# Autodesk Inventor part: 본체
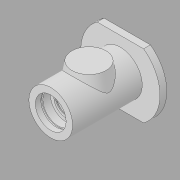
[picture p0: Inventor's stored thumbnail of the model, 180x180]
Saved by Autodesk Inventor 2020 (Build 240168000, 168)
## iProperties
Created: 2022-05
Part Number: 본체
Material: 일반
Document SubType Name: Modeling
Designer: User
Density: 1 g/cm^3
Appearance: 기본값
Author: User
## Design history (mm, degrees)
sketch "스케치1"
  geometry: L1 (-125, -47)-(125, -47); L2 (125, -47)-(125, 47); L3 (125, 47)-(-125, 47); L4 (-125, 47)-(-125, -47); L5 (-125, -47)-(125, 47); L6 (125, -47)-(-125, 47); C1 r 58 at (0, 0); 5 further points
  constraints: 12 end point, 2 midpoint, 2 parallel, 1 centre point, 1 coincident, 1 horizontal, 1 perpendicular
  dimensions: "d0" = 116 diameter of C1; "d1" = 94 distance between parallel lines of L1 L3; "d2" = 250 distance between parallel lines of L4 L2
extrude "돌출1" new body sketch "스케치1" distance "d3" = 10; taper "d4" = 0 deg
sketch "스케치3"
  geometry: C1 r 36 at (0, 0); 1 further point
  constraints: 1 centre point, 1 coincident
  dimensions: "d5" = 72 diameter of C1
extrude "돌출2" join sketch "스케치3" distance "d6" = 3; taper "d7" = 0 deg
sketch "스케치4"
  geometry: L1 (-36, -3)-(36, -3) reference; L2 (0, -3)-(-32, -3); L3 (-32, -3)-(-32, 112); L4 (-32, 112)-(0, 112); L5 (0, 112)-(0, -3); L6 (-22.5, 112)-(-22.5, 104); L7 (-22.5, 104)-(-24, 104); L8 (-24, 104)-(-24, 101); L9 (-24, 101)-(-22.5, 101); L10 (-22.5, 101)-(-22.5, 90); L11 (-22.5, 90)-(-17.5, 90); L12 (-17.5, 90)-(-17.5, 87.75); L13 (-17.5, 87.75)-(-18.5, 87.75); L14 (-18.5, 87.75)-(-18.5, 86); L15 (-18.5, 86)-(-17.5, 86); L16 (-17.5, 86)-(-17.5, 75); L17 (-17.5, 75)-(-27, 75); L18 (-27, 75)-(-27, 37); L19 (-27, 37)-(-17.5, 37); L20 (-17.5, 37)-(-17.5, 26); L21 (-17.5, 26)-(-15, 26); L22 (-15, 26)-(-15, 21); L23 (-15, 21)-(-11, 21); L24 (-11, 21)-(-11, 18.3); L25 (-11, 18.3)-(-15, 18.3); L26 (-15, 18.3)-(-15, 11); L27 (-15, 11)-(-20, 11); L28 (-20, 11)-(-30, -3); 3 further points
  constraints: 54 end point, 18 perpendicular, 5 point on line, 3 parallel, 3 vertical, 1 horizontal, 1 midpoint
  dimensions: "d8" = 115 distance of L2.end L3.end; "d9" = 64 diameter of L3 L5; "d10" = 48 diameter of L8 L5; "d11" = 45 diameter of L10 L5; "d12" = 45 diameter of L6 L5; "d13" = 37 diameter of L14 L5; "d14" = 35 diameter of L12 L5; "d15" = 54 diameter of L18 L5; "d16" = 30 diameter of L22 L5; "d17" = 22 diameter of L24 L5; "d18" = 30 diameter of L26 L5; "d19" = 60 diameter of L28.end L5; "d20" = 8 distance of L6.start L6.end; "d21" = 3 distance of L7.end L8.end; "d22" = 22 distance between parallel lines of L11 L4; "d23" = 1.75 distance of L13.end L14.end; "d24" = 4 distance between parallel lines of L15 L11; "d25" = 11 distance from line of L17 L15.end; "d26" = 38 distance between parallel lines of L19 L17; "d27" = 11 distance between parallel lines of L21 L19; "d28" = 5 distance between parallel lines of L23 L21; "d29" = 14 distance between parallel lines of L2 L27; "d30" = 7.3 distance between parallel lines of L25 L27; "d31" = 40 diameter of L27.end L5
revolve "회전1" stored, may be unused: angle "d32" = 90 deg
revolve "회전2" stored, may be unused: angle "d33" = 90 deg
node "작업 평면1"
sketch "스케치5"
  geometry: L1 (32, 112)-(-32, 112) reference; L2 (-33.985, 0)-(33.985, 0) reference; C1 r 25 at (0, 56); 2 further points
  constraints: 1 centre point, 1 midpoint, 1 vertical alignment
  dimensions: "d35" = 56 distance from line of C1.centre L1; "d36" = 50 diameter of C1
extrude "돌출3" join sketch "스케치5" stored distance "d37" = 3; taper "d38" = 10 deg
node "솔리드1"
other parameters: "d34" = -38
